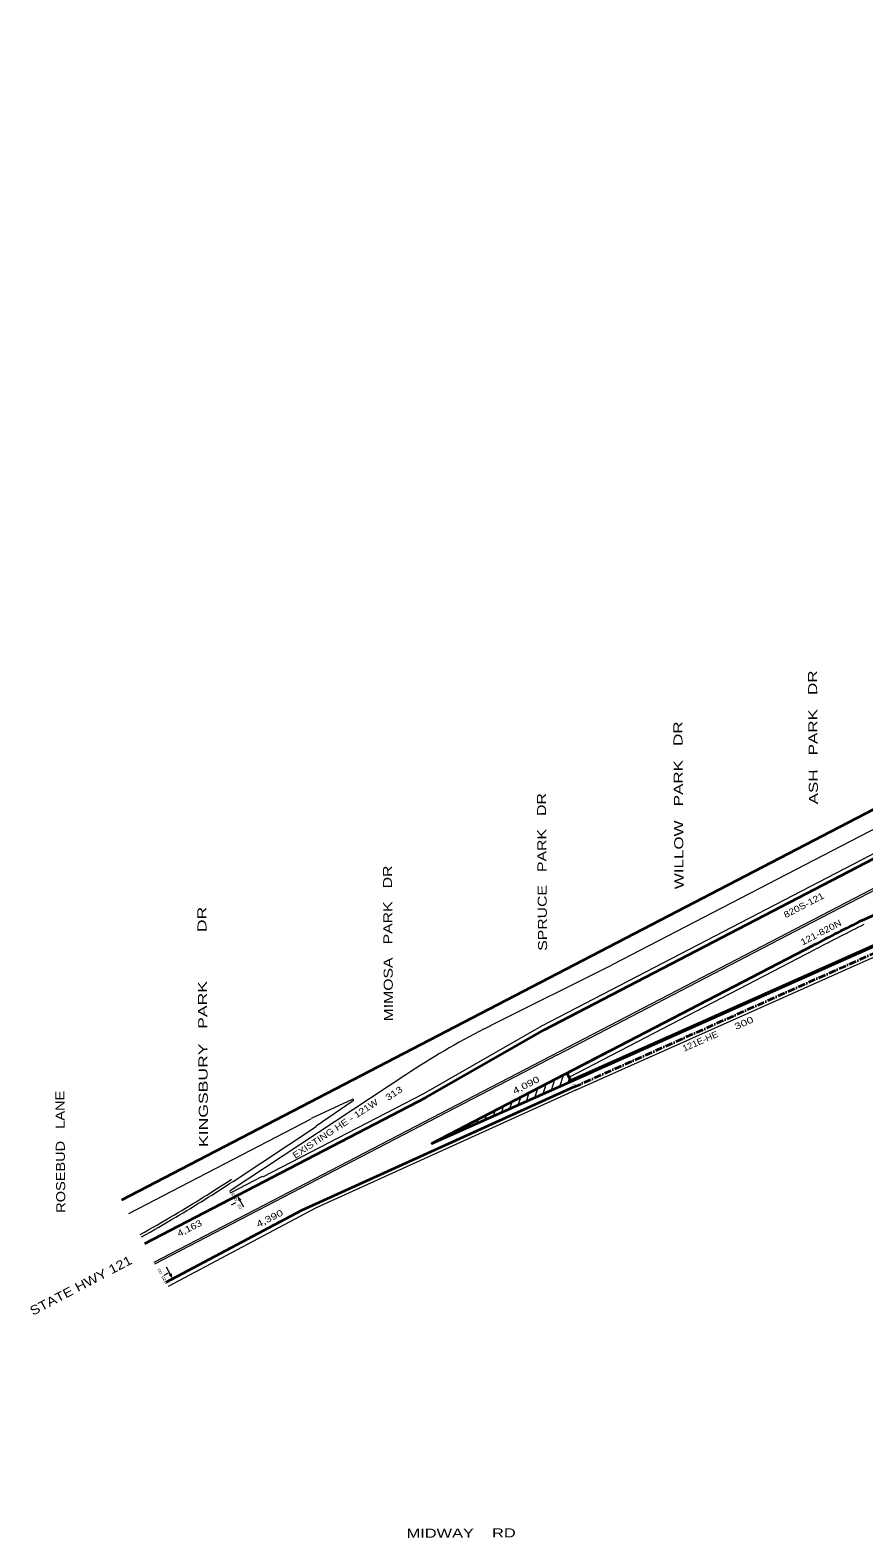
# Model space of a CAD drawing. Extents: x 2354993 to 2372084, y 6966390 to 6990057.
# Drawn here: x 2357805 to 2359644, y 6975175 to 6978502 of the extents above; entities that cross this region are included whole.
import ezdxf
from ezdxf.enums import TextEntityAlignment as Align

# ---------------------------------------------------------------- set-up
doc = ezdxf.new("R2010")
doc.units = 0
doc.header["$LTSCALE"] = 3.2
doc.linetypes.add('DOT_DASHED', pattern=[7.7, 5, -1.2, 0.3, -1.2])
for name, color, linetype, lineweight in [('1', 7, 'Continuous', 13), ('13', 7, 'Continuous', 13), ('19', 7, 'Continuous', 13), ('2', 7, 'Continuous', 35), ('5', 7, 'Continuous', 35), ('6', 7, 'Continuous', 35)]:
    doc.layers.add(name, color=color, linetype=linetype, lineweight=lineweight)

msp = doc.modelspace()

# ---------------------------------------------------------------- linework, layer by layer
at = {"layer": '1'}
for p, q in [((2359006.156, 6976170.14), (2359002.656, 6976170.14)), ((2359004.406, 6976171.89), (2359004.406, 6976168.39))]:
    msp.add_line(p, q, dxfattribs=at)
at = {"layer": '19'}
for p, q in [((2358263.451, 6975927.231), (2358269.311, 6975921.338)), ((2358257.883, 6975914.634), (2358248.229, 6975909.692)), ((2358108.871, 6975759.062), (2358099.217, 6975754.12)), ((2358117.435, 6975750.727), (2358111.575, 6975756.62))]:
    msp.add_line(p, q, dxfattribs=at)
for points in [[(2358275.922, 6975904.666), (2358263.451, 6975927.231), (2358265.323, 6975919.139)], [(2358104.964, 6975773.292), (2358117.435, 6975750.727), (2358115.563, 6975758.819)]]:
    msp.add_lwpolyline(points, dxfattribs=at)
at = {"layer": '2'}
msp.add_line((2358006.591, 6975920.846), (2363488.891, 6978770.331), dxfattribs=at)
at = {"layer": '5', "lineweight": 13}
for p, q in [((2358077.838, 6975783.754), (2361546.398, 6977586.361)), ((2359089.137, 6976440.054), (2360420.126, 6977131.769)), ((2359530.419, 6976533.69), (2360298.445, 6976932.155)), ((2358933.627, 6976305.141), (2359820.865, 6976766.238)), ((2358967.505, 6976241.142), (2359530.42, 6976533.69)), ((2358993.329, 6976191.453), (2359537.036, 6976474.019)), ((2358820.159, 6976305.907), (2359088.663, 6976439.813)), ((2358672.686, 6976156.007), (2358933.627, 6976305.141)), ((2358805.935, 6976298.51), (2358820.634, 6976306.149)), ((2358967.505, 6976241.142), (2358079.021, 6975779.395)), ((2358633.618, 6976197.166), (2358246.128, 6975941.075)), ((2358954.627, 6976163.248), (2358961.958, 6976186.419)), ((2358972.948, 6976171.428), (2358980.787, 6976196.204)), ((2358991.269, 6976179.606), (2358994.378, 6976189.432)), ((2358318.21, 6975971.786), (2358672.686, 6976156.007)), ((2358899.666, 6976138.712), (2358905.472, 6976157.062)), ((2358917.987, 6976146.891), (2358924.3, 6976166.848)), ((2358936.307, 6976155.07), (2358943.129, 6976176.633)), ((2358515.067, 6976142.836), (2358424.255, 6976100.543)), ((2358517.041, 6976139.373), (2358435.469, 6976083.473)), ((2358844.704, 6976114.176), (2358848.985, 6976127.706)), ((2358863.025, 6976122.354), (2358867.814, 6976137.492)), ((2358881.346, 6976130.534), (2358886.643, 6976147.277)), ((2358022.04, 6975891.12), (2358424.402, 6976100.227)), ((2358771.422, 6976081.46), (2358773.67, 6976088.565)), ((2358789.743, 6976089.639), (2358792.499, 6976098.35)), ((2358808.063, 6976097.818), (2358811.327, 6976108.136)), ((2358826.383, 6976105.996), (2358830.157, 6976117.921)), ((2358252.191, 6975961.934), (2358435.66, 6976083.195)), ((2358716.46, 6976056.924), (2358717.184, 6976059.209)), ((2358734.781, 6976065.103), (2358736.012, 6976068.994)), ((2358753.102, 6976073.282), (2358754.841, 6976078.779)), ((2358248.153, 6975937.631), (2358317.288, 6975973.56))]:
    msp.add_line(p, q, dxfattribs=at)
at = {"layer": '5'}
for p, q in [((2359639.244, 6976537.697), (2360535.509, 6976941.217)), ((2358938.418, 6976296.361), (2359825.476, 6976757.364)), ((2358988.717, 6976200.325), (2359532.424, 6976482.891)), ((2358677.486, 6976147.231), (2358938.418, 6976296.361)), ((2358988.717, 6976200.325), (2358997.937, 6976182.583)), ((2358057.742, 6975825.151), (2358677.486, 6976147.231))]:
    msp.add_line(p, q, dxfattribs=at)
for points in [[(2359074.954, 6976245.143), (2358690.408, 6976045.293), (2359043.674, 6976203.002)], [(2359004.406, 6976170.14), (2358403.252, 6975897.744), (2358104.115, 6975738.428)]]:
    msp.add_lwpolyline(points, dxfattribs=at)
at = {"layer": '5', "lineweight": 13}
msp.add_lwpolyline([(2359007.708, 6976162.854), (2358435.287, 6975903.477), (2358108.816, 6975729.602)], dxfattribs=at)
at = {"layer": '5'}
msp.add_arc((2364816.681, 6966315.035), 11459, 116.86069, 117.461, dxfattribs=at)
at = {"layer": '5', "lineweight": 13}
for centre, radius, start, end in [((2364816.681, 6966315.035), 11449, 116.86184, 117.461), ((2359686.645, 6974603.838), 1909.859, 117.46061, 123.46061), ((2358515.911, 6976141.023), 2, 304.4226, 114.97127), ((2356672.597, 6978351.892), 2858.789, 300.4899, 303.4619), ((2356672.597, 6978351.892), 2864.789, 300.4899, 303.4619), ((2358247.23, 6975939.406), 2, 123.46043, 297.46082), ((2355219.042, 6980820.534), 5723.578, 299.61371, 300.4899), ((2355219.042, 6980820.534), 5729.578, 299.61216, 300.4899)]:
    msp.add_arc(centre, radius, start, end, dxfattribs=at)
at = {"layer": '6', "lineweight": 13}
for p, q in [((2358997.069, 6976186.577), (2359959.749, 6976616.346)), ((2359007.668, 6976162.836), (2359970.348, 6976592.605))]:
    msp.add_line(p, q, dxfattribs=at)
at = {"layer": '6'}
msp.add_line((2358998.699, 6976182.924), (2359961.379, 6976612.693), dxfattribs=at)
at = {"layer": '6', "linetype": 'DOT_DASHED'}
msp.add_line((2359004.406, 6976170.14), (2359967.083, 6976599.908), dxfattribs=at)
msp.add_line((2359004.406, 6976170.14), (2359967.083, 6976599.908), dxfattribs=at)

# ---------------------------------------------------------------- texts
at = {"layer": '13'}
for s, rotation, width, p in [('ASH   PARK   DR', 90.423, 1.4, (2359541.365, 6976941.541)), ('WILLOW   PARK   DR', 90.423, 1.4, (2359244.663, 6976791.681)), ('SPRUCE   PARK   DR', 90.423, 1.3, (2358943.65, 6976644.63)), ('MIMOSA   PARK   DR', 90.423, 1.3, (2358603.871, 6976486.85)), ('KINGSBURY   PARK          DR', 90.423, 1.45, (2358195.301, 6976302.861)), ('ROSEBUD   LANE', 90.423, 1.2, (2357881.24, 6976027.245)), ('MIDWAY    RD', 0.248, 1.35, (2358755.398, 6975175.863))]:
    msp.add_text(s, height=20, rotation=rotation, dxfattribs=dict(at, width=width)).set_placement(p, align=Align.CENTER)
for s, height, rotation, width, p in [('820S-121', 14, 27.565, 1.2, (2359471.174, 6976542.426)), ('121-820N', 14, 27.565, 1.2, (2359508.502, 6976482.218)), ('300', 14, 24.081, 1.4, (2359361.843, 6976295.936)), ('121E-HE', 14, 23.865, 1.1, (2359247.326, 6976247.88)), ('4,090', 14, 27.116, 1.35, (2358873.431, 6976153.711)), ('313', 14, 33.539, 1.3, (2358593.959, 6976138.966)), ('EXISTING HE - 121W', 14, 33.37, 1.2, (2358389.251, 6976011.562)), ('4,390', 14, 26.715, 1.35, (2358307.785, 6975859.762)), ('4,163', 14, 26.715, 1.25, (2358132.993, 6975839.141)), ('STATE HWY 121', 20, 27.695, 1.2, (2357810.589, 6975665.294))]:
    msp.add_text(s, height=height, rotation=rotation, dxfattribs=dict(at, width=width)).set_placement(p)
at = {"layer": '19'}
for s, rotation, width, p in [('.025', 120.786, 1.4, (2358263.979, 6975918.65)), ('.02', 117.124, 1.3, (2358273.307, 6975899.9)), ('.02', 117.124, 1.3, (2358097.2, 6975757.317)), ('.025', 120.786, 1.4, (2358109.891, 6975735.514))]:
    msp.add_text(s, height=6, rotation=rotation, dxfattribs=dict(at, width=width)).set_placement(p)
at = {"layer": '2', "width": 1.15}
msp.add_text('F25', height=3.5, dxfattribs=at).set_placement((2358999.818, 6976172.34))

doc.saveas('drawing.dxf')
